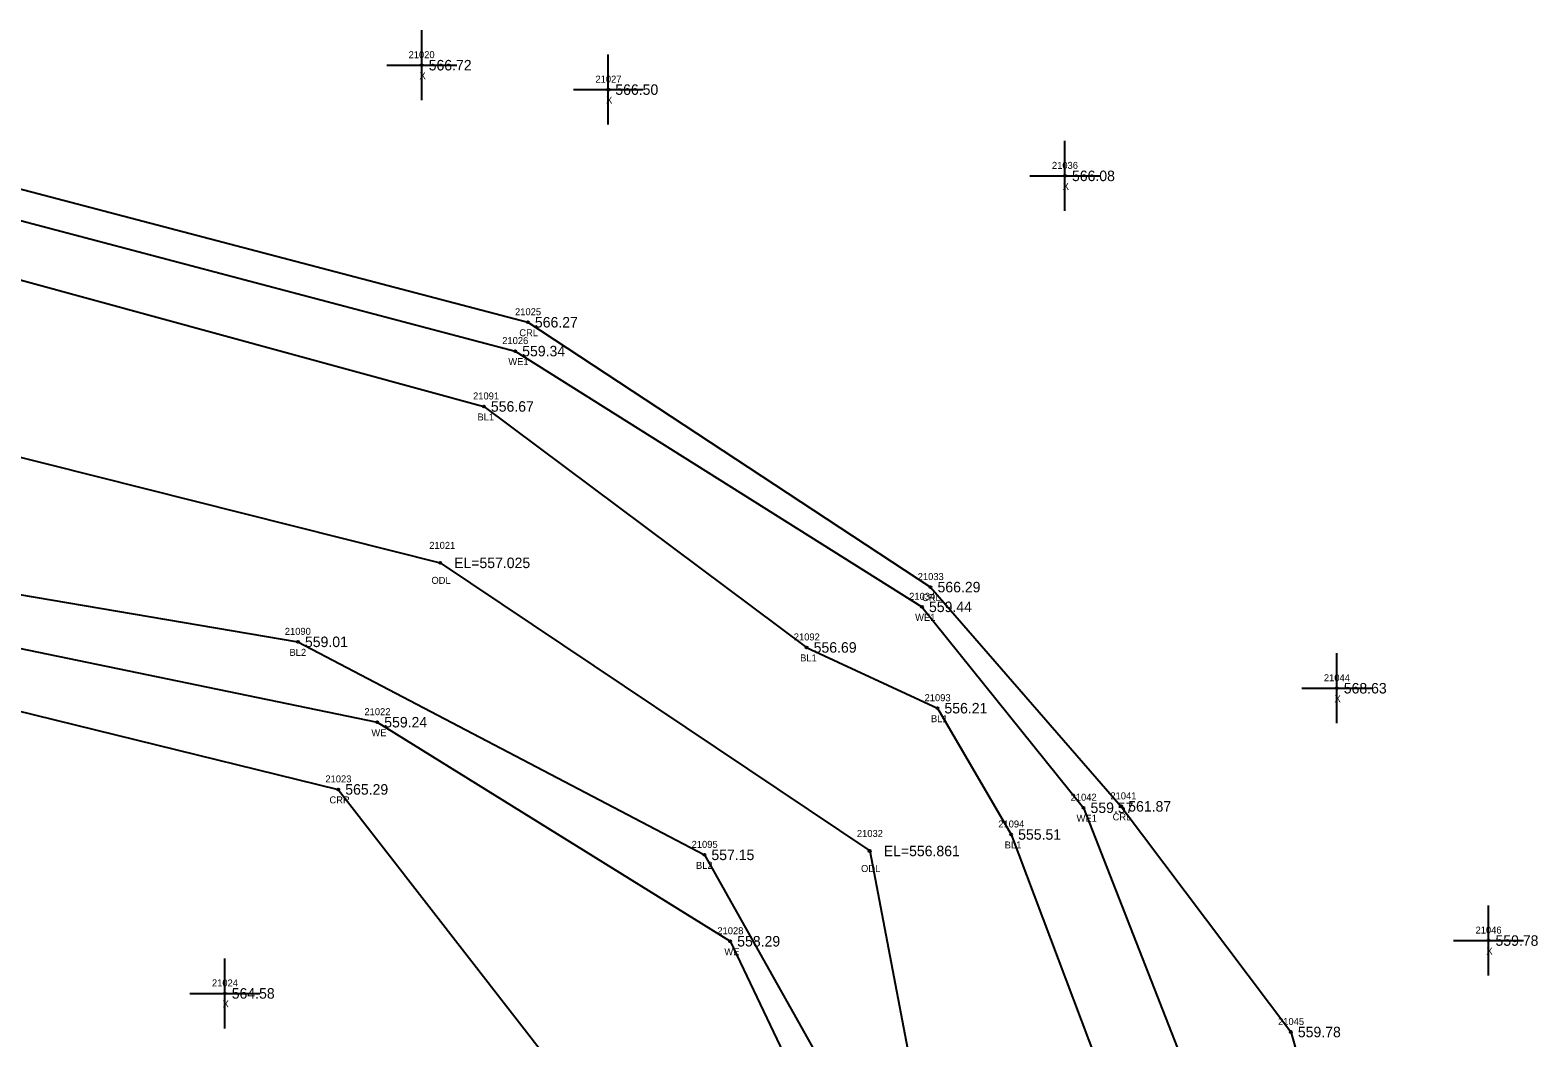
# Model space of a CAD drawing. Extents: x 1695443 to 1696344, y 1087542 to 1090645.
# Drawn here: x 1696093 to 1696308.5, y 1089047 to 1089190.9 of the extents above; entities that cross this region are included whole.
import ezdxf

# ---------------------------------------------------------------- set-up
doc = ezdxf.new("R2010")
doc.units = 0
for name, color, linetype in [('RD_DTM_BkLn1', 7, 'Continuous'), ('RD_DTM_BkLn_txCode', 7, 'Continuous'), ('RD_EX_H2O', 7, 'Continuous'), ('RD_EX_H2O_txCode', 7, 'Continuous'), ('RD_EX_Misc', 7, 'Continuous'), ('RD_EX_Misc_txCode', 7, 'Continuous'), ('RD_EX_TX_H2O_ELEV', 7, 'Continuous'), ('RD_EX_TX_Misc_ELEV', 7, 'Continuous'), ('RD_SMD_Locator', 7, 'Continuous')]:
    doc.layers.add(name, color=color, linetype=linetype)

msp = doc.modelspace()

# ---------------------------------------------------------------- linework, layer by layer
at = {"layer": 'RD_DTM_BkLn1'}
for points in [[(1695477.93, 1088750.04), (1695615.7, 1088831.98), (1695678.81, 1088884.02), (1695727.39, 1088931.9), (1695787.9, 1089007.61), (1695838.8, 1089064.32), (1695878.44, 1089095.49), (1695937, 1089135.88), (1696036.12, 1089170.43), (1696157.88, 1089137.18), (1696204, 1089102.76), (1696222.69, 1089094.08), (1696233.22, 1089076.04), (1696249.95, 1089031.73), (1696253.49, 1088951.92)], [(1695519.05, 1088717.19), (1695621.07, 1088784.34), (1695706.03, 1088842.06), (1695754.64, 1088904.72), (1695822.43, 1088986.95), (1695872.19, 1089035.65), (1695897.24, 1089064.09), (1695953.83, 1089097.9), (1696039.66, 1089119.12), (1696131.31, 1089103.56), (1696189.39, 1089073.13), (1696217.04, 1089023.97), (1696212.37, 1088964.66)]]:
    msp.add_lwpolyline(points, dxfattribs=at)
at = {"layer": 'RD_EX_H2O'}
for points in [[(1695741.44, 1088979.77), (1695766.31, 1089008.66), (1695772.21, 1089014.13), (1695837.09, 1089090.39), (1695860.76, 1089111.44), (1695929.31, 1089152.28), (1696035.3, 1089183.03), (1696164.17, 1089149.21), (1696221.7, 1089111.38), (1696248.95, 1089080.06), (1696273.19, 1089047.83), (1696283.59, 1089011.28), (1696295.68, 1088944.39)], [(1695466.3, 1088756.42), (1695582.06, 1088826.6), (1695651.04, 1088873.87), (1695702.34, 1088921.12), (1695742.91, 1088967.28), (1695775.02, 1089011.92), (1695840.03, 1089086.93), (1695863.99, 1089105.53), (1695935.01, 1089145.27), (1696036.06, 1089178.39), (1696162.35, 1089145.09), (1696220.48, 1089108.56), (1696243.56, 1089079.86), (1696260.75, 1089035.89), (1696273.81, 1089006.71), (1696286.66, 1088942.65)], [(1695498.69, 1088725.6), (1695608.54, 1088797.54), (1695668.72, 1088841.78), (1695723.76, 1088906.07), (1695797.15, 1088991.78), (1695861.15, 1089050.89), (1695886.72, 1089073.86), (1695948.49, 1089109.39), (1696039, 1089143.17), (1696151.62, 1089114.84), (1696213.01, 1089073.69), (1696220.87, 1089032.47), (1696230.14, 1088992.72), (1696246.9, 1088917.69)], [(1695518.5, 1088708.22), (1695626.45, 1088775.86), (1695695.79, 1088824.57), (1695753.51, 1088889.68), (1695821.81, 1088964.67), (1695880.24, 1089030.4), (1695903.5, 1089050.75), (1695958.92, 1089087.13), (1696042.79, 1089112.69), (1696142.64, 1089092.08), (1696193.08, 1089060.79), (1696207.36, 1089030.79), (1696205.38, 1088967.18), (1696218.5, 1088901.4)], [(1695520.92, 1088704.05), (1695627.53, 1088770.84), (1695697.51, 1088817.15), (1695757.08, 1088884.85), (1695828.4, 1088961.5), (1695887.69, 1089025.09), (1695910.13, 1089043.49), (1695963.83, 1089083.42), (1696041.69, 1089105.91), (1696137.07, 1089082.48), (1696174.24, 1089034.61), (1696185.76, 1089011.54), (1696200.45, 1088973.14), (1696214.06, 1088899.28)]]:
    msp.add_lwpolyline(points, dxfattribs=at)
at = {"layer": 'RD_EX_Misc'}
for p, q in [((1696148.99, 1089180.93), (1696148.99, 1089190.93)), ((1696143.99, 1089185.93), (1696153.99, 1089185.93)), ((1696175.66, 1089177.44), (1696175.66, 1089187.44)), ((1696170.66, 1089182.44), (1696180.66, 1089182.44)), ((1696240.91, 1089165.12), (1696240.91, 1089175.12)), ((1696235.91, 1089170.12), (1696245.91, 1089170.12)), ((1696279.75, 1089091.93), (1696279.75, 1089101.93)), ((1696274.75, 1089096.93), (1696284.75, 1089096.93)), ((1696301.43, 1089055.89), (1696301.43, 1089065.89)), ((1696296.43, 1089060.89), (1696306.43, 1089060.89)), ((1696120.85, 1089048.34), (1696120.85, 1089058.34)), ((1696115.85, 1089053.34), (1696125.85, 1089053.34))]:
    msp.add_line(p, q, dxfattribs=at)
at = {"layer": 'RD_SMD_Locator'}
for centre in [(1696148.99, 1089185.93), (1696175.66, 1089182.44), (1696240.91, 1089170.12), (1696164.17, 1089149.21), (1696162.35, 1089145.09), (1696157.88, 1089137.18), (1696151.62, 1089114.84), (1696221.7, 1089111.38), (1696220.48, 1089108.56), (1696131.31, 1089103.56), (1696204, 1089102.76), (1696279.75, 1089096.93), (1696222.69, 1089094.08), (1696142.64, 1089092.08), (1696137.07, 1089082.48), (1696248.95, 1089080.06), (1696243.56, 1089079.86), (1696233.22, 1089076.04), (1696213.01, 1089073.69), (1696189.39, 1089073.13), (1696193.08, 1089060.79), (1696301.43, 1089060.89), (1696120.85, 1089053.34), (1696273.19, 1089047.83)]:
    msp.add_circle(centre, 0.15, dxfattribs=at)

# ---------------------------------------------------------------- texts
at = {"layer": 'RD_DTM_BkLn_txCode'}
for s, p in [('21091', (1696156.33, 1089138.18)), ('BL1', (1696156.96, 1089135.18)), ('21090', (1696129.43, 1089104.56)), ('21092', (1696202.16, 1089103.76)), ('BL2', (1696130.1, 1089101.56)), ('BL1', (1696203.07, 1089100.76)), ('21093', (1696220.85, 1089095.08)), ('BL1', (1696221.76, 1089092.08)), ('21094', (1696231.38, 1089077.04)), ('21095', (1696187.56, 1089074.13)), ('BL1', (1696232.3, 1089074.04)), ('BL2', (1696188.19, 1089071.13))]:
    msp.add_text(s, height=1, dxfattribs=at).set_placement(p)
at = {"layer": 'RD_EX_H2O_txCode'}
for s, p in [('21025', (1696162.33, 1089150.21)), ('21026', (1696160.5, 1089146.09)), ('CRL', (1696162.94, 1089147.21)), ('WE1', (1696161.37, 1089143.09)), ('21021', (1696150.07, 1089116.84)), ('ODL', (1696150.38, 1089111.84)), ('21033', (1696219.87, 1089112.38)), ('21034', (1696218.65, 1089109.56)), ('CRL', (1696220.48, 1089109.38)), ('WE1', (1696219.5, 1089106.56)), ('21022', (1696140.81, 1089093.08)), ('WE', (1696141.8, 1089090.08)), ('21023', (1696135.23, 1089083.48)), ('CRR', (1696135.81, 1089080.48)), ('21042', (1696241.72, 1089080.86)), ('21041', (1696247.4, 1089081.06)), ('WE1', (1696242.57, 1089077.86)), ('CRL', (1696247.72, 1089078.06)), ('21032', (1696211.18, 1089075.69)), ('ODL', (1696211.77, 1089070.69)), ('21028', (1696191.24, 1089061.79)), ('WE', (1696192.24, 1089058.79)), ('21045', (1696271.36, 1089048.83))]:
    msp.add_text(s, height=1, dxfattribs=at).set_placement(p)
at = {"layer": 'RD_EX_Misc_txCode'}
for s, p in [('21020', (1696147.12, 1089186.93)), ('X', (1696148.68, 1089183.93)), ('21027', (1696173.82, 1089183.44)), ('X', (1696175.34, 1089180.44)), ('21036', (1696239.05, 1089171.12)), ('X', (1696240.59, 1089168.12)), ('21044', (1696277.91, 1089097.93)), ('X', (1696279.43, 1089094.93)), ('21046', (1696299.58, 1089061.89)), ('X', (1696301.12, 1089058.89)), ('21024', (1696119.02, 1089054.34)), ('X', (1696120.54, 1089051.34))]:
    msp.add_text(s, height=1, dxfattribs=at).set_placement(p)
at = {"layer": 'RD_EX_TX_H2O_ELEV'}
for s, p in [('566.27', (1696165.17, 1089148.46)), ('559.34', (1696163.35, 1089144.34)), ('EL=557.025', (1696153.62, 1089114.09)), ('566.29', (1696222.7, 1089110.63)), ('559.44', (1696221.48, 1089107.81)), ('559.24', (1696143.64, 1089091.33)), ('565.29', (1696138.07, 1089081.73)), ('559.57', (1696244.56, 1089079.11)), ('561.87', (1696249.95, 1089079.31)), ('EL=556.861', (1696215.01, 1089072.94)), ('558.29', (1696194.08, 1089060.04)), ('559.78', (1696274.19, 1089047.08))]:
    msp.add_text(s, height=1.5, dxfattribs=at).set_placement(p)
at = {"layer": 'RD_EX_TX_Misc_ELEV'}
for s, p in [('566.72', (1696149.99, 1089185.18)), ('566.50', (1696176.66, 1089181.69)), ('566.08', (1696241.91, 1089169.37)), ('556.67', (1696158.88, 1089136.43)), ('559.01', (1696132.31, 1089102.81)), ('556.69', (1696205, 1089102.01)), ('568.63', (1696280.75, 1089096.18)), ('556.21', (1696223.69, 1089093.33)), ('555.51', (1696234.22, 1089075.29)), ('557.15', (1696190.39, 1089072.38)), ('559.78', (1696302.43, 1089060.14)), ('564.58', (1696121.85, 1089052.59))]:
    msp.add_text(s, height=1.5, dxfattribs=at).set_placement(p)

doc.saveas('drawing.dxf')
